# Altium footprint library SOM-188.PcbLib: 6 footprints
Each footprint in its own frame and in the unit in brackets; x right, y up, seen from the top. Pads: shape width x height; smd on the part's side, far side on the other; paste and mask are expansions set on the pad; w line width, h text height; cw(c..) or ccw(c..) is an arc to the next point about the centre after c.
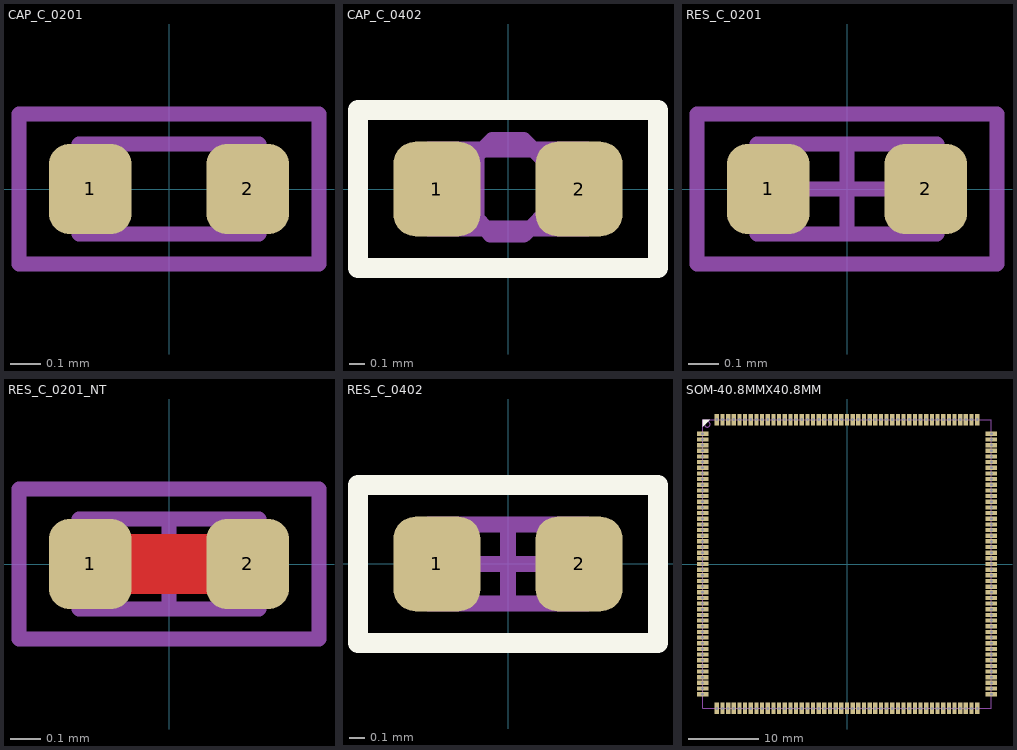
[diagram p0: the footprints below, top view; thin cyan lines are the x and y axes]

## CAP_C_0201 [mm] "Chip Capacitor, 2-Leads, Body 0.6x0.3mm, IPC Medium Density"
height 0.3
pads (2):
  rrect50% 0.275x0.3 smd mask+0.05: 1(-0.262,0) 2(0.262,0)
Assy TOP (M11):
  lines w0.05: -0.3,-0.15 0.3,-0.15 0.3,0.15 -0.3,0.15 -0.3,-0.15
  text ".Designator" at -0.25,-0.1 h0.2
Guard TOP (M15):
  lines w0.05: -0.5,-0.25 -0.5,0.25 0.5,0.25 0.5,-0.25 -0.5,-0.25
  text "C" at -0.075,-0.1 h0.2
3D body "User Library-SMD CAPACITOR.STEP": height 0.28, standoff -0.02, extent -0.3,-0.15 0.3,0.15

## CAP_C_0402 [mm] "Chip Capacitor, 2-Leads, Body 1.0x0.5mm, IPC High Density"
height 0.5
pads (2):
  rrect50% 0.55x0.6 smd: 1(-0.45,0) 2(0.45,0)
Top Overlay:
  lines w0.125: -0.95,-0.5 0.95,-0.5 0.95,0.5 -0.95,0.5 -0.95,-0.5
Assy TOP (M11):
  lines w0.1: -0.5,-0.25 0.5,-0.25 0.5,0.25 -0.5,0.25 -0.5,-0.25
  text ".Designator" at -0.4,-0.15 h0.3
3D TOP (M13):
  lines w0.1: -0.5,-0.25 -0.5,0.25 0.5,0.25 0.5,-0.25 -0.5,-0.25
Guard TOP (M15):
  lines w0.1: 0.2,-0.19 0.1,-0.29 -0.11,-0.29 -0.2,-0.18 -0.2,0.21 -0.1,0.31 0.1,0.31 0.2,0.21 ; -0.95,-0.5 -0.95,0.5 0.95,0.5 0.95,-0.5 -0.95,-0.5
3D body "CAP_C_0402.step": height 0.2, standoff 0, extent -0.5,-0.3 0.5,0.3

## RES_C_0201 [mm] "Chip Resistor, 2-Leads, Body 0.6x0.3mm, IPC Medium Density"
height 0.23
pads (2):
  rrect50% 0.275x0.3 smd mask+0.05: 1(-0.262,0) 2(0.262,0)
Assy TOP (M11):
  lines w0.05: -0.3,-0.15 -0.3,0.15 0.3,0.15 0.3,-0.15 -0.3,-0.15
  text ".Designator" at -0.25,-0.1 h0.2
Guard TOP (M15):
  lines w0.05: -0.125,0 0.125,0 ; 0,-0.125 0,0.125 ; -0.5,-0.25 0.5,-0.25 0.5,0.25 -0.5,0.25 -0.5,-0.25
3D body "User Library-SMD RESISTOR-10201.STEP": height 0.22, standoff -0.01, extent -0.3,-0.15 0.3,0.15

## RES_C_0201_NT [mm] "Chip Resistor, 2-Leads, Body 0.6x0.3mm, IPC Medium Density"
height 0.23
pads (2):
  rrect50% 0.275x0.3 smd mask+0.05: 1(-0.262,0) 2(0.262,0)
Top Layer:
  lines w0.2: -0.262,0 0.262,0
Assy TOP (M11):
  lines w0.05: -0.3,-0.15 0.3,-0.15 0.3,0.15 -0.3,0.15 -0.3,-0.15
  text ".Designator" at -0.25,-0.1 h0.2
Guard TOP (M15):
  lines w0.05: -0.125,0 0.125,0 ; 0,-0.125 0,0.125 ; -0.5,-0.25 -0.5,0.25 0.5,0.25 0.5,-0.25 -0.5,-0.25
3D body "User Library-SMD RESISTOR-10201.STEP": height 0.22, standoff -0.01, extent -0.3,-0.15 0.3,0.15

## RES_C_0402 [mm] "Chip Resistor, 2-Leads, Body 1.0x0.5mm, IPC Medium Density"
height 0.35
pads (2):
  rrect50% 0.55x0.6 smd: 1(-0.45,0) 2(0.45,0)
Top Overlay:
  lines w0.125: -0.95,-0.5 0.95,-0.5 0.95,0.5 -0.95,0.5 -0.95,-0.5
Assy TOP (M11):
  lines w0.1: -0.5,-0.25 0.5,-0.25 0.5,0.25 -0.5,0.25 -0.5,-0.25
  text ".Designator" at -0.4,-0.15 h0.3
3D TOP (M13):
  lines w0.1: -0.5,-0.25 -0.5,0.25 0.5,0.25 0.5,-0.25 -0.5,-0.25
Guard TOP (M15):
  lines w0.1: -0.25,0 0.25,0 ; 0,-0.25 0,0.25 ; -0.95,-0.5 -0.95,0.5 0.95,0.5 0.95,-0.5 -0.95,-0.5
3D body "RES_0402.step": height 0.2, standoff 0, extent -0.5,-0.3 0.5,0.3

## SOM-40.8MMX40.8MM [mm] "188-Castellated thru-holes"
pads (188):
  rect 1.6x0.6 / inner rect 1.6x0.6 / far side rect 3x0.6 hole 0.4 mask+0.05: 1(-20.4,18.4) 2(-20.4,17.6) 3(-20.4,16.8) 4(-20.4,16) 5(-20.4,15.2) 6(-20.4,14.4) 7(-20.4,13.6) 8(-20.4,12.8) 9(-20.4,12) 10(-20.4,11.2) 11(-20.4,10.4) 12(-20.4,9.6) 13(-20.4,8.8) 14(-20.4,8) 15(-20.4,7.2) 16(-20.4,6.4) 17(-20.4,5.6) 18(-20.4,4.8) 19(-20.4,4) 20(-20.4,3.2) 21(-20.4,2.4) 22(-20.4,1.6) 23(-20.4,0.8) 24(-20.4,0) 25(-20.4,-0.8) 26(-20.4,-1.6) 27(-20.4,-2.4) 28(-20.4,-3.2) 29(-20.4,-4) 30(-20.4,-4.8) 31(-20.4,-5.6) 32(-20.4,-6.4) 33(-20.4,-7.2) 34(-20.4,-8) 35(-20.4,-8.8) 36(-20.4,-9.6) 37(-20.4,-10.4) 38(-20.4,-11.2) 39(-20.4,-12) 40(-20.4,-12.8) 41(-20.4,-13.6) 42(-20.4,-14.4) 43(-20.4,-15.2) 44(-20.4,-16) 45(-20.4,-16.8) 46(-20.4,-17.6) 47(-20.4,-18.4) 95(20.4,-18.4) 96(20.4,-17.6) 97(20.4,-16.8) 98(20.4,-16) 99(20.4,-15.2) 100(20.4,-14.4) 101(20.4,-13.6) 102(20.4,-12.8) 103(20.4,-12) 104(20.4,-11.2) 105(20.4,-10.4) 106(20.4,-9.6) 107(20.4,-8.8) 108(20.4,-8) 109(20.4,-7.2) 110(20.4,-6.4) 111(20.4,-5.6) 112(20.4,-4.8) 113(20.4,-4) 114(20.4,-3.2) 115(20.4,-2.4) 116(20.4,-1.6) 117(20.4,-0.8) 118(20.4,0) 119(20.4,0.8) 120(20.4,1.6) 121(20.4,2.4) 122(20.4,3.2) 123(20.4,4) 124(20.4,4.8) 125(20.4,5.6) 126(20.4,6.4) 127(20.4,7.2) 128(20.4,8) 129(20.4,8.8) 130(20.4,9.6) 131(20.4,10.4) 132(20.4,11.2) 133(20.4,12) 134(20.4,12.8) 135(20.4,13.6) 136(20.4,14.4) 137(20.4,15.2) 138(20.4,16) 139(20.4,16.8) 140(20.4,17.6) 141(20.4,18.4)
  rect 0.6x1.6 / inner rect 0.6x1.6 / far side rect 0.6x3 hole 0.4 mask+0.05: 48(-18.4,-20.4) 49(-17.6,-20.4) 50(-16.8,-20.4) 51(-16,-20.4) 52(-15.2,-20.4) 53(-14.4,-20.4) 54(-13.6,-20.4) 55(-12.8,-20.4) 56(-12,-20.4) 57(-11.2,-20.4) 58(-10.4,-20.4) 59(-9.6,-20.4) 60(-8.8,-20.4) 61(-8,-20.4) 62(-7.2,-20.4) 63(-6.4,-20.4) 64(-5.6,-20.4) 65(-4.8,-20.4) 66(-4,-20.4) 67(-3.2,-20.4) 68(-2.4,-20.4) 69(-1.6,-20.4) 70(-0.8,-20.4) 71(0,-20.4) 72(0.8,-20.4) 73(1.6,-20.4) 74(2.4,-20.4) 75(3.2,-20.4) 76(4,-20.4) 77(4.8,-20.4) 78(5.6,-20.4) 79(6.4,-20.4) 80(7.2,-20.4) 81(8,-20.4) 82(8.8,-20.4) 83(9.6,-20.4) 84(10.4,-20.4) 85(11.2,-20.4) 86(12,-20.4) 87(12.8,-20.4) 88(13.6,-20.4) 89(14.4,-20.4) 90(15.2,-20.4) 91(16,-20.4) 92(16.8,-20.4) 93(17.6,-20.4) 94(18.4,-20.4) 142(18.4,20.4) 143(17.6,20.4) 144(16.8,20.4) 145(16,20.4) 146(15.2,20.4) 147(14.4,20.4) 148(13.6,20.4) 149(12.8,20.4) 150(12,20.4) 151(11.2,20.4) 152(10.4,20.4) 153(9.6,20.4) 154(8.8,20.4) 155(8,20.4) 156(7.2,20.4) 157(6.4,20.4) 158(5.6,20.4) 159(4.8,20.4) 160(4,20.4) 161(3.2,20.4) 162(2.4,20.4) 163(1.6,20.4) 164(0.8,20.4) 165(0,20.4) 166(-0.8,20.4) 167(-1.6,20.4) 168(-2.4,20.4) 169(-3.2,20.4) 170(-4,20.4) 171(-4.8,20.4) 172(-5.6,20.4) 173(-6.4,20.4) 174(-7.2,20.4) 175(-8,20.4) 176(-8.8,20.4) 177(-9.6,20.4) 178(-10.4,20.4) 179(-11.2,20.4) 180(-12,20.4) 181(-12.8,20.4) 182(-13.6,20.4) 183(-14.4,20.4) 184(-15.2,20.4) 185(-16,20.4) 186(-16.8,20.4) 187(-17.6,20.4) 188(-18.4,20.4)
Top Overlay:
  region: -20.4,20.4 -19.4,20.4 -20.4,19.4
Bottom Overlay:
  region: -20.4,20.4 -19.4,20.4 -20.4,19.4
Assy TOP (M11):
  circle w0.01: c-19.75,19.75 r0.4
  lines w0.01: -20.4,-20.4 -20.4,20.4 20.4,20.4 20.4,-20.4 -20.4,-20.4
  text "1" at -20.1,18.175 h0.4
3D body: height 0.04, standoff 0, extent 18.9,18.1 20.4,18.7
3D body: height 0.04, standoff 0, extent 18.9,17.3 20.4,17.9
3D body: height 0.04, standoff 0, extent 18.9,16.5 20.4,17.1
3D body: height 0.04, standoff 0, extent 18.9,15.7 20.4,16.3
3D body: height 0.04, standoff 0, extent 18.9,14.9 20.4,15.5
3D body: height 0.04, standoff 0, extent 18.9,14.1 20.4,14.7
3D body: height 0.04, standoff 0, extent 18.9,13.3 20.4,13.9
3D body: height 0.04, standoff 0, extent 18.9,12.5 20.4,13.1
3D body: height 0.04, standoff 0, extent 18.9,11.7 20.4,12.3
3D body: height 0.04, standoff 0, extent 18.9,10.9 20.4,11.5
3D body: height 0.04, standoff 0, extent 18.9,10.1 20.4,10.7
3D body: height 0.04, standoff 0, extent 18.9,9.3 20.4,9.9
3D body: height 0.04, standoff 0, extent 18.9,8.5 20.4,9.1
3D body: height 0.04, standoff 0, extent 18.9,7.7 20.4,8.3
3D body: height 0.04, standoff 0, extent 18.9,6.9 20.4,7.5
3D body: height 0.04, standoff 0, extent 18.9,6.1 20.4,6.7
3D body: height 0.04, standoff 0, extent 18.9,5.3 20.4,5.9
3D body: height 0.04, standoff 0, extent 18.9,4.5 20.4,5.1
3D body: height 0.04, standoff 0, extent 18.9,3.7 20.4,4.3
3D body: height 0.04, standoff 0, extent 18.9,2.9 20.4,3.5
3D body: height 0.04, standoff 0, extent 18.9,2.1 20.4,2.7
3D body: height 0.04, standoff 0, extent 18.9,1.3 20.4,1.9
3D body: height 0.04, standoff 0, extent 18.9,0.5 20.4,1.1
3D body: height 0.04, standoff 0, extent 18.9,-0.3 20.4,0.3
3D body: height 0.04, standoff 0, extent 18.9,-1.1 20.4,-0.5
3D body: height 0.04, standoff 0, extent 18.9,-1.9 20.4,-1.3
3D body: height 0.04, standoff 0, extent 18.9,-2.7 20.4,-2.1
3D body: height 0.04, standoff 0, extent 18.9,-3.5 20.4,-2.9
3D body: height 0.04, standoff 0, extent 18.9,-4.3 20.4,-3.7
3D body: height 0.04, standoff 0, extent 18.9,-5.1 20.4,-4.5
3D body: height 0.04, standoff 0, extent 18.9,-5.9 20.4,-5.3
3D body: height 0.04, standoff 0, extent 18.9,-6.7 20.4,-6.1
3D body: height 0.04, standoff 0, extent 18.9,-7.5 20.4,-6.9
3D body: height 0.04, standoff 0, extent 18.9,-8.3 20.4,-7.7
3D body: height 0.04, standoff 0, extent 18.9,-9.1 20.4,-8.5
3D body: height 0.04, standoff 0, extent 18.9,-9.9 20.4,-9.3
3D body: height 0.04, standoff 0, extent 18.9,-10.7 20.4,-10.1
3D body: height 0.04, standoff 0, extent 18.9,-11.5 20.4,-10.9
3D body: height 0.04, standoff 0, extent 18.9,-12.3 20.4,-11.7
3D body: height 0.04, standoff 0, extent 18.9,-13.1 20.4,-12.5
3D body: height 0.04, standoff 0, extent 18.9,-13.9 20.4,-13.3
3D body: height 0.04, standoff 0, extent 18.9,-14.7 20.4,-14.1
3D body: height 0.04, standoff 0, extent 18.9,-15.5 20.4,-14.9
3D body: height 0.04, standoff 0, extent 18.9,-16.3 20.4,-15.7
3D body: height 0.04, standoff 0, extent 18.9,-17.1 20.4,-16.5
3D body: height 0.04, standoff 0, extent 18.9,-17.9 20.4,-17.3
3D body: height 0.04, standoff 0, extent 18.9,-18.7 20.4,-18.1
3D body: height 0.04, standoff 0, extent -18.7,18.9 -18.1,20.4
3D body: height 0.04, standoff 0, extent -17.9,18.9 -17.3,20.4
3D body: height 0.04, standoff 0, extent -17.1,18.9 -16.5,20.4
3D body: height 0.04, standoff 0, extent -16.3,18.9 -15.7,20.4
3D body: height 0.04, standoff 0, extent -15.5,18.9 -14.9,20.4
3D body: height 0.04, standoff 0, extent -14.7,18.9 -14.1,20.4
3D body: height 0.04, standoff 0, extent -13.9,18.9 -13.3,20.4
3D body: height 0.04, standoff 0, extent -13.1,18.9 -12.5,20.4
3D body: height 0.04, standoff 0, extent -12.3,18.9 -11.7,20.4
3D body: height 0.04, standoff 0, extent -11.5,18.9 -10.9,20.4
3D body: height 0.04, standoff 0, extent -10.7,18.9 -10.1,20.4
3D body: height 0.04, standoff 0, extent -9.9,18.9 -9.3,20.4
3D body: height 0.04, standoff 0, extent -9.1,18.9 -8.5,20.4
3D body: height 0.04, standoff 0, extent -8.3,18.9 -7.7,20.4
3D body: height 0.04, standoff 0, extent -7.5,18.9 -6.9,20.4
3D body: height 0.04, standoff 0, extent -6.7,18.9 -6.1,20.4
3D body: height 0.04, standoff 0, extent -5.9,18.9 -5.3,20.4
3D body: height 0.04, standoff 0, extent -5.1,18.9 -4.5,20.4
3D body: height 0.04, standoff 0, extent -4.3,18.9 -3.7,20.4
3D body: height 0.04, standoff 0, extent -3.5,18.9 -2.9,20.4
3D body: height 0.04, standoff 0, extent -2.7,18.9 -2.1,20.4
3D body: height 0.04, standoff 0, extent -1.9,18.9 -1.3,20.4
3D body: height 0.04, standoff 0, extent -1.1,18.9 -0.5,20.4
3D body: height 0.04, standoff 0, extent -0.3,18.9 0.3,20.4
3D body: height 0.04, standoff 0, extent 0.5,18.9 1.1,20.4
3D body: height 0.04, standoff 0, extent 1.3,18.9 1.9,20.4
3D body: height 0.04, standoff 0, extent 2.1,18.9 2.7,20.4
3D body: height 0.04, standoff 0, extent 2.9,18.9 3.5,20.4
3D body: height 0.04, standoff 0, extent 3.7,18.9 4.3,20.4
3D body: height 0.04, standoff 0, extent 4.5,18.9 5.1,20.4
3D body: height 0.04, standoff 0, extent 5.3,18.9 5.9,20.4
3D body: height 0.04, standoff 0, extent 6.1,18.9 6.7,20.4
3D body: height 0.04, standoff 0, extent 6.9,18.9 7.5,20.4
3D body: height 0.04, standoff 0, extent 7.7,18.9 8.3,20.4
3D body: height 0.04, standoff 0, extent 8.5,18.9 9.1,20.4
3D body: height 0.04, standoff 0, extent 9.3,18.9 9.9,20.4
3D body: height 0.04, standoff 0, extent 10.1,18.9 10.7,20.4
3D body: height 0.04, standoff 0, extent 10.9,18.9 11.5,20.4
3D body: height 0.04, standoff 0, extent 11.7,18.9 12.3,20.4
3D body: height 0.04, standoff 0, extent 12.5,18.9 13.1,20.4
3D body: height 0.04, standoff 0, extent 13.3,18.9 13.9,20.4
3D body: height 0.04, standoff 0, extent 14.1,18.9 14.7,20.4
3D body: height 0.04, standoff 0, extent 14.9,18.9 15.5,20.4
3D body: height 0.04, standoff 0, extent 15.7,18.9 16.3,20.4
3D body: height 0.04, standoff 0, extent 16.5,18.9 17.1,20.4
3D body: height 0.04, standoff 0, extent 17.3,18.9 17.9,20.4
3D body: height 0.04, standoff 0, extent 18.1,18.9 18.7,20.4
3D body: height 0.04, standoff 0, extent -18.7,-20.4 -18.1,-18.9
3D body: height 0.04, standoff 0, extent -17.9,-20.4 -17.3,-18.9
3D body: height 0.04, standoff 0, extent -17.1,-20.4 -16.5,-18.9
3D body: height 0.04, standoff 0, extent -16.3,-20.4 -15.7,-18.9
3D body: height 0.04, standoff 0, extent -15.5,-20.4 -14.9,-18.9
3D body: height 0.04, standoff 0, extent -14.7,-20.4 -14.1,-18.9
3D body: height 0.04, standoff 0, extent -13.9,-20.4 -13.3,-18.9
3D body: height 0.04, standoff 0, extent -13.1,-20.4 -12.5,-18.9
3D body: height 0.04, standoff 0, extent -12.3,-20.4 -11.7,-18.9
3D body: height 0.04, standoff 0, extent -11.5,-20.4 -10.9,-18.9
3D body: height 0.04, standoff 0, extent -10.7,-20.4 -10.1,-18.9
3D body: height 0.04, standoff 0, extent -9.9,-20.4 -9.3,-18.9
3D body: height 0.04, standoff 0, extent -9.1,-20.4 -8.5,-18.9
3D body: height 0.04, standoff 0, extent -8.3,-20.4 -7.7,-18.9
3D body: height 0.04, standoff 0, extent -7.5,-20.4 -6.9,-18.9
3D body: height 0.04, standoff 0, extent -6.7,-20.4 -6.1,-18.9
3D body: height 0.04, standoff 0, extent -5.9,-20.4 -5.3,-18.9
3D body: height 0.04, standoff 0, extent -5.1,-20.4 -4.5,-18.9
3D body: height 0.04, standoff 0, extent -4.3,-20.4 -3.7,-18.9
3D body: height 0.04, standoff 0, extent -3.5,-20.4 -2.9,-18.9
3D body: height 0.04, standoff 0, extent -2.7,-20.4 -2.1,-18.9
3D body: height 0.04, standoff 0, extent -1.9,-20.4 -1.3,-18.9
3D body: height 0.04, standoff 0, extent -1.1,-20.4 -0.5,-18.9
3D body: height 0.04, standoff 0, extent -0.3,-20.4 0.3,-18.9
3D body: height 0.04, standoff 0, extent 0.5,-20.4 1.1,-18.9
3D body: height 0.04, standoff 0, extent 1.3,-20.4 1.9,-18.9
3D body: height 0.04, standoff 0, extent 2.1,-20.4 2.7,-18.9
3D body: height 0.04, standoff 0, extent 2.9,-20.4 3.5,-18.9
3D body: height 0.04, standoff 0, extent 3.7,-20.4 4.3,-18.9
3D body: height 0.04, standoff 0, extent 4.5,-20.4 5.1,-18.9
3D body: height 0.04, standoff 0, extent 5.3,-20.4 5.9,-18.9
3D body: height 0.04, standoff 0, extent 6.1,-20.4 6.7,-18.9
3D body: height 0.04, standoff 0, extent 6.9,-20.4 7.5,-18.9
3D body: height 0.04, standoff 0, extent 7.7,-20.4 8.3,-18.9
3D body: height 0.04, standoff 0, extent 8.5,-20.4 9.1,-18.9
3D body: height 0.04, standoff 0, extent 9.3,-20.4 9.9,-18.9
3D body: height 0.04, standoff 0, extent 10.1,-20.4 10.7,-18.9
3D body: height 0.04, standoff 0, extent 10.9,-20.4 11.5,-18.9
3D body: height 0.04, standoff 0, extent 11.7,-20.4 12.3,-18.9
3D body: height 0.04, standoff 0, extent 12.5,-20.4 13.1,-18.9
3D body: height 0.04, standoff 0, extent 13.3,-20.4 13.9,-18.9
3D body: height 0.04, standoff 0, extent 14.1,-20.4 14.7,-18.9
3D body: height 0.04, standoff 0, extent 14.9,-20.4 15.5,-18.9
3D body: height 0.04, standoff 0, extent 15.7,-20.4 16.3,-18.9
3D body: height 0.04, standoff 0, extent 16.5,-20.4 17.1,-18.9
3D body: height 0.04, standoff 0, extent 17.3,-20.4 17.9,-18.9
3D body: height 0.04, standoff 0, extent 18.1,-20.4 18.7,-18.9
3D body: height 0.04, standoff 0, extent -20.4,-18.7 -18.9,-18.1
3D body: height 0.04, standoff 0, extent -20.4,-17.9 -18.9,-17.3
3D body: height 0.04, standoff 0, extent -20.4,-17.1 -18.9,-16.5
3D body: height 0.04, standoff 0, extent -20.4,-16.3 -18.9,-15.7
3D body: height 0.04, standoff 0, extent -20.4,-15.5 -18.9,-14.9
3D body: height 0.04, standoff 0, extent -20.4,-14.7 -18.9,-14.1
3D body: height 0.04, standoff 0, extent -20.4,-13.9 -18.9,-13.3
3D body: height 0.04, standoff 0, extent -20.4,-13.1 -18.9,-12.5
3D body: height 0.04, standoff 0, extent -20.4,-12.3 -18.9,-11.7
3D body: height 0.04, standoff 0, extent -20.4,-11.5 -18.9,-10.9
3D body: height 0.04, standoff 0, extent -20.4,-10.7 -18.9,-10.1
3D body: height 0.04, standoff 0, extent -20.4,-9.9 -18.9,-9.3
3D body: height 0.04, standoff 0, extent -20.4,-9.1 -18.9,-8.5
3D body: height 0.04, standoff 0, extent -20.4,-8.3 -18.9,-7.7
3D body: height 0.04, standoff 0, extent -20.4,-7.5 -18.9,-6.9
3D body: height 0.04, standoff 0, extent -20.4,-6.7 -18.9,-6.1
3D body: height 0.04, standoff 0, extent -20.4,-5.9 -18.9,-5.3
3D body: height 0.04, standoff 0, extent -20.4,-5.1 -18.9,-4.5
3D body: height 0.04, standoff 0, extent -20.4,-4.3 -18.9,-3.7
3D body: height 0.04, standoff 0, extent -20.4,-3.5 -18.9,-2.9
3D body: height 0.04, standoff 0, extent -20.4,-2.7 -18.9,-2.1
3D body: height 0.04, standoff 0, extent -20.4,-1.9 -18.9,-1.3
3D body: height 0.04, standoff 0, extent -20.4,-1.1 -18.9,-0.5
3D body: height 0.04, standoff 0, extent -20.4,-0.3 -18.9,0.3
3D body: height 0.04, standoff 0, extent -20.4,0.5 -18.9,1.1
3D body: height 0.04, standoff 0, extent -20.4,1.3 -18.9,1.9
3D body: height 0.04, standoff 0, extent -20.4,2.1 -18.9,2.7
3D body: height 0.04, standoff 0, extent -20.4,2.9 -18.9,3.5
3D body: height 0.04, standoff 0, extent -20.4,3.7 -18.9,4.3
3D body: height 0.04, standoff 0, extent -20.4,4.5 -18.9,5.1
3D body: height 0.04, standoff 0, extent -20.4,5.3 -18.9,5.9
3D body: height 0.04, standoff 0, extent -20.4,6.1 -18.9,6.7
3D body: height 0.04, standoff 0, extent -20.4,6.9 -18.9,7.5
3D body: height 0.04, standoff 0, extent -20.4,7.7 -18.9,8.3
3D body: height 0.04, standoff 0, extent -20.4,8.5 -18.9,9.1
3D body: height 0.04, standoff 0, extent -20.4,9.3 -18.9,9.9
3D body: height 0.04, standoff 0, extent -20.4,10.1 -18.9,10.7
3D body: height 0.04, standoff 0, extent -20.4,10.9 -18.9,11.5
3D body: height 0.04, standoff 0, extent -20.4,11.7 -18.9,12.3
3D body: height 0.04, standoff 0, extent -20.4,12.5 -18.9,13.1
3D body: height 0.04, standoff 0, extent -20.4,13.3 -18.9,13.9
3D body: height 0.04, standoff 0, extent -20.4,14.1 -18.9,14.7
3D body: height 0.04, standoff 0, extent -20.4,14.9 -18.9,15.5
3D body: height 0.04, standoff 0, extent -20.4,15.7 -18.9,16.3
3D body: height 0.04, standoff 0, extent -20.4,16.5 -18.9,17.1
3D body: height 0.04, standoff 0, extent -20.4,17.3 -18.9,17.9
3D body: height 0.04, standoff 0, extent -20.4,18.1 -18.9,18.7
3D body: height 0.04, standoff 0, extent -20.4,19.4 -19.4,20.4
3D body: height 0.04, standoff 0, extent -20.4,19.4 -19.4,20.4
